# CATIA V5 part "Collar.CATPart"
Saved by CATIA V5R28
Part number: Collar
Material "Orange": density 7860 kg/m3, Young's modulus 2e+11 Pa, Poisson ratio 0.266
Bounding box of the stored display mesh (mm): x -12.5 to 12.5, y -12.5 to 12.5, z -5 to 5
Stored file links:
  C:\Users\Parisa\Desktop\tarah sanat\Universal Coupling\Collar.CATPart
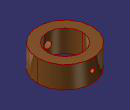
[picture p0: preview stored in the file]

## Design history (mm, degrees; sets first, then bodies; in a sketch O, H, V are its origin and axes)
Body1 "Collar" (main body), material "Orange"
  Sketch1 on xy-plane, origin (0, 0, 0), H (1, 0, 0), V (0, 1, 0)
    circle A1 centre (0, 0) radius 12.5
    circle A2 centre (0, 0) radius 8
    radius A1 = 12.5
    radius A2 = 8
  Pad1: profile Sketch1, direction (0, 0, 1), length 5, mirrored extent
  Sketch2 on yz-plane, origin (0, 0, 0), H (0, 1, 0), V (0, 0, 1)
    line L1 (0, 0) -> (15, 0)
    point P1 (15, 0)
    point P2 (-15, 0)
    point P3 (0, 0)
    line L2 (0, 0) -> (-15, 0)
    line L3 (-15, 0) -> (-15, 2)
    line L4 (-15, 2) -> (15, 0.9996)
    line L5 (15, 0.9996) -> (15, 0)
    length L1 = 15
    length L3 = 2
    angle L3 L4 = 88.09
    horizontal: L1 H
    symmetry: P1 P2 V, O P3 V, L1 L2 V
    vertical: L3 V, L5 V
    coincidence: O P3
  Groove1: profile Sketch2, axis Sketch2.L2, angle 360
